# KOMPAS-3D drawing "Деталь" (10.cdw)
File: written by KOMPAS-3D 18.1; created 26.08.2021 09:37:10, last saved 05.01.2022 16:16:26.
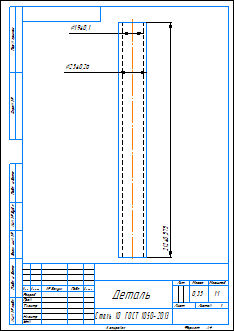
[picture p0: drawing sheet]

Sheet 1: A4, portrait

Document properties: Автор: 111; Полное имя файла: C:\Users\admin\Desktop\ffb\10.cdw; Масса: 0.345327

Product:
- Part/product: Деталь
    Масса: 0.345327
    source file: ..\10.cdw
  - Component: Отверстие  | qty 2

Title block, sheet 1: Наименование: Деталь; Материал: Сталь 10  ГОСТ 1050-2013; Масса: 0,35; Количество листов документа: 1; Форматы листов документа: A4; stored path: H:\Desktop\_\10.cdw

Views: Вид 1, Спереди
Referenced files in C:\Users\admin\Desktop\ffb\: 5.m3d
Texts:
  Отверстие
Dimensions and other numbers on the sheet: 212±0,575; 19±0,1; 25±0,26; 1:1; 1; 0,35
